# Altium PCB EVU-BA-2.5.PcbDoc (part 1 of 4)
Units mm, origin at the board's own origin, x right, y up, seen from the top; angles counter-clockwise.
Board outline 80 x 82.5 mm, 4 copper layers (Top Layer, Int1, Int2, Bottom Layer), stack 1.49 mm thick; 257 components, 201 nets, 889 pads, 696 vias.
Unrouted connection lines stored in the file: 1.
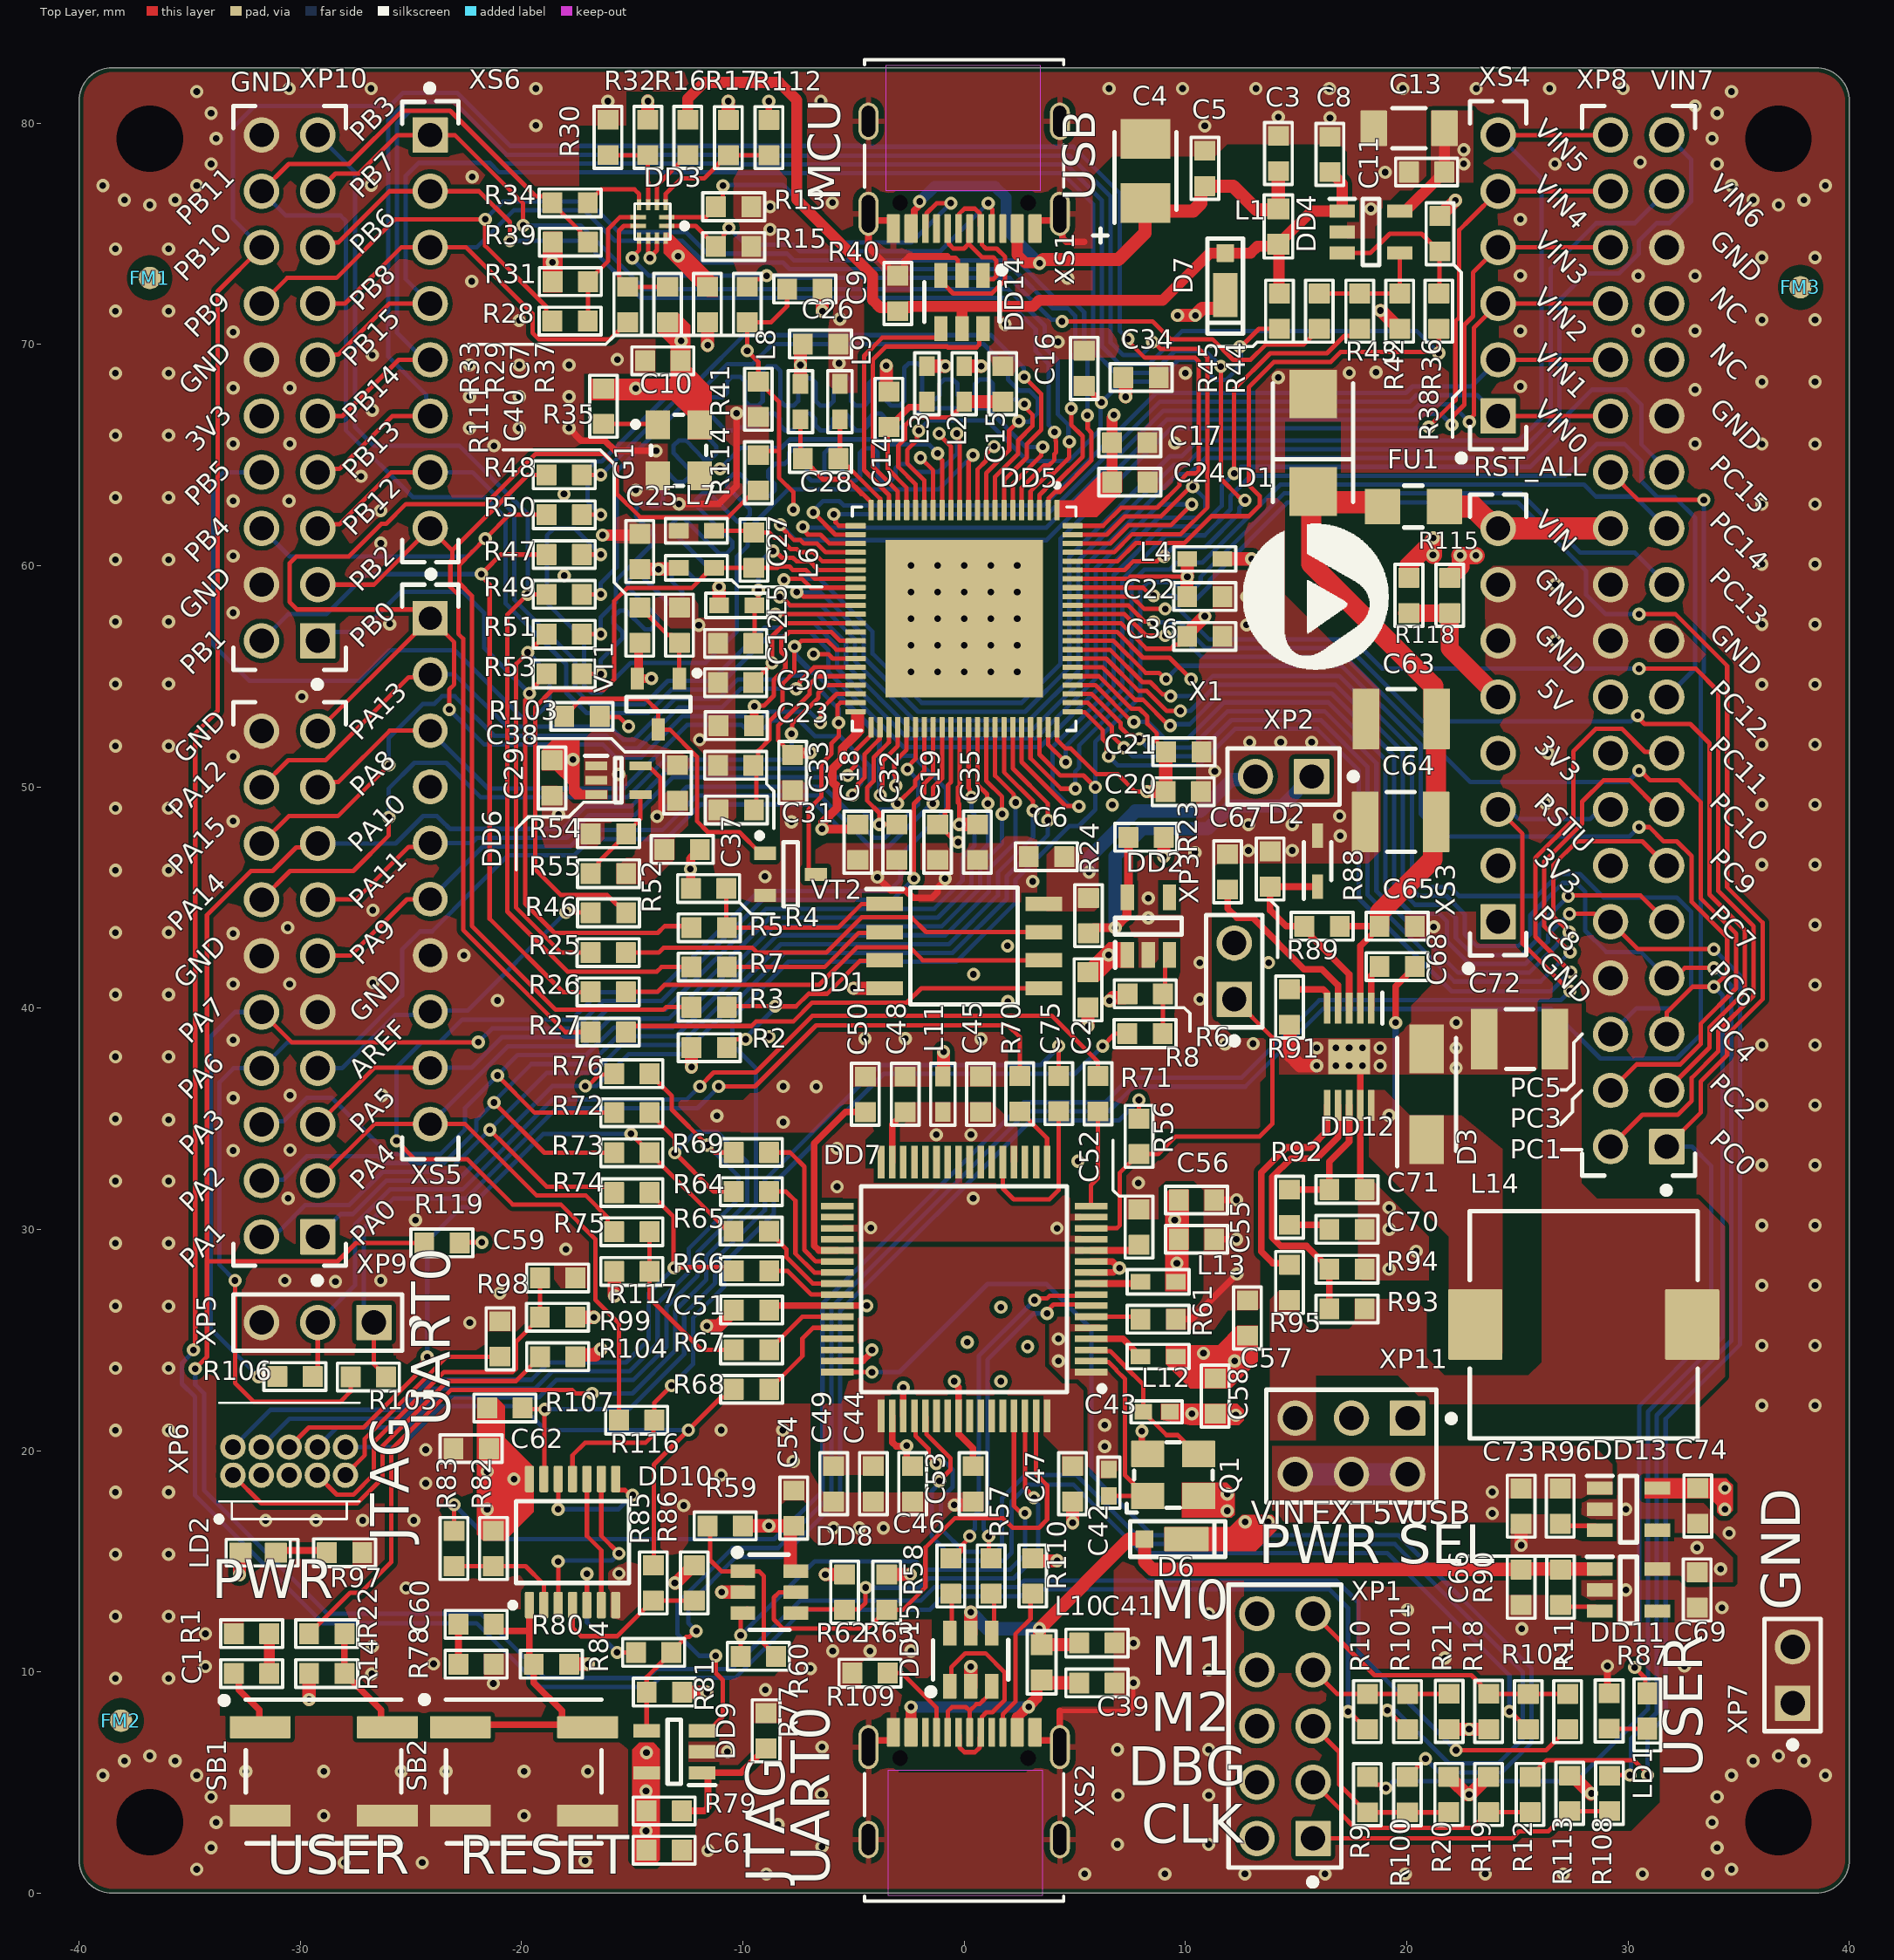
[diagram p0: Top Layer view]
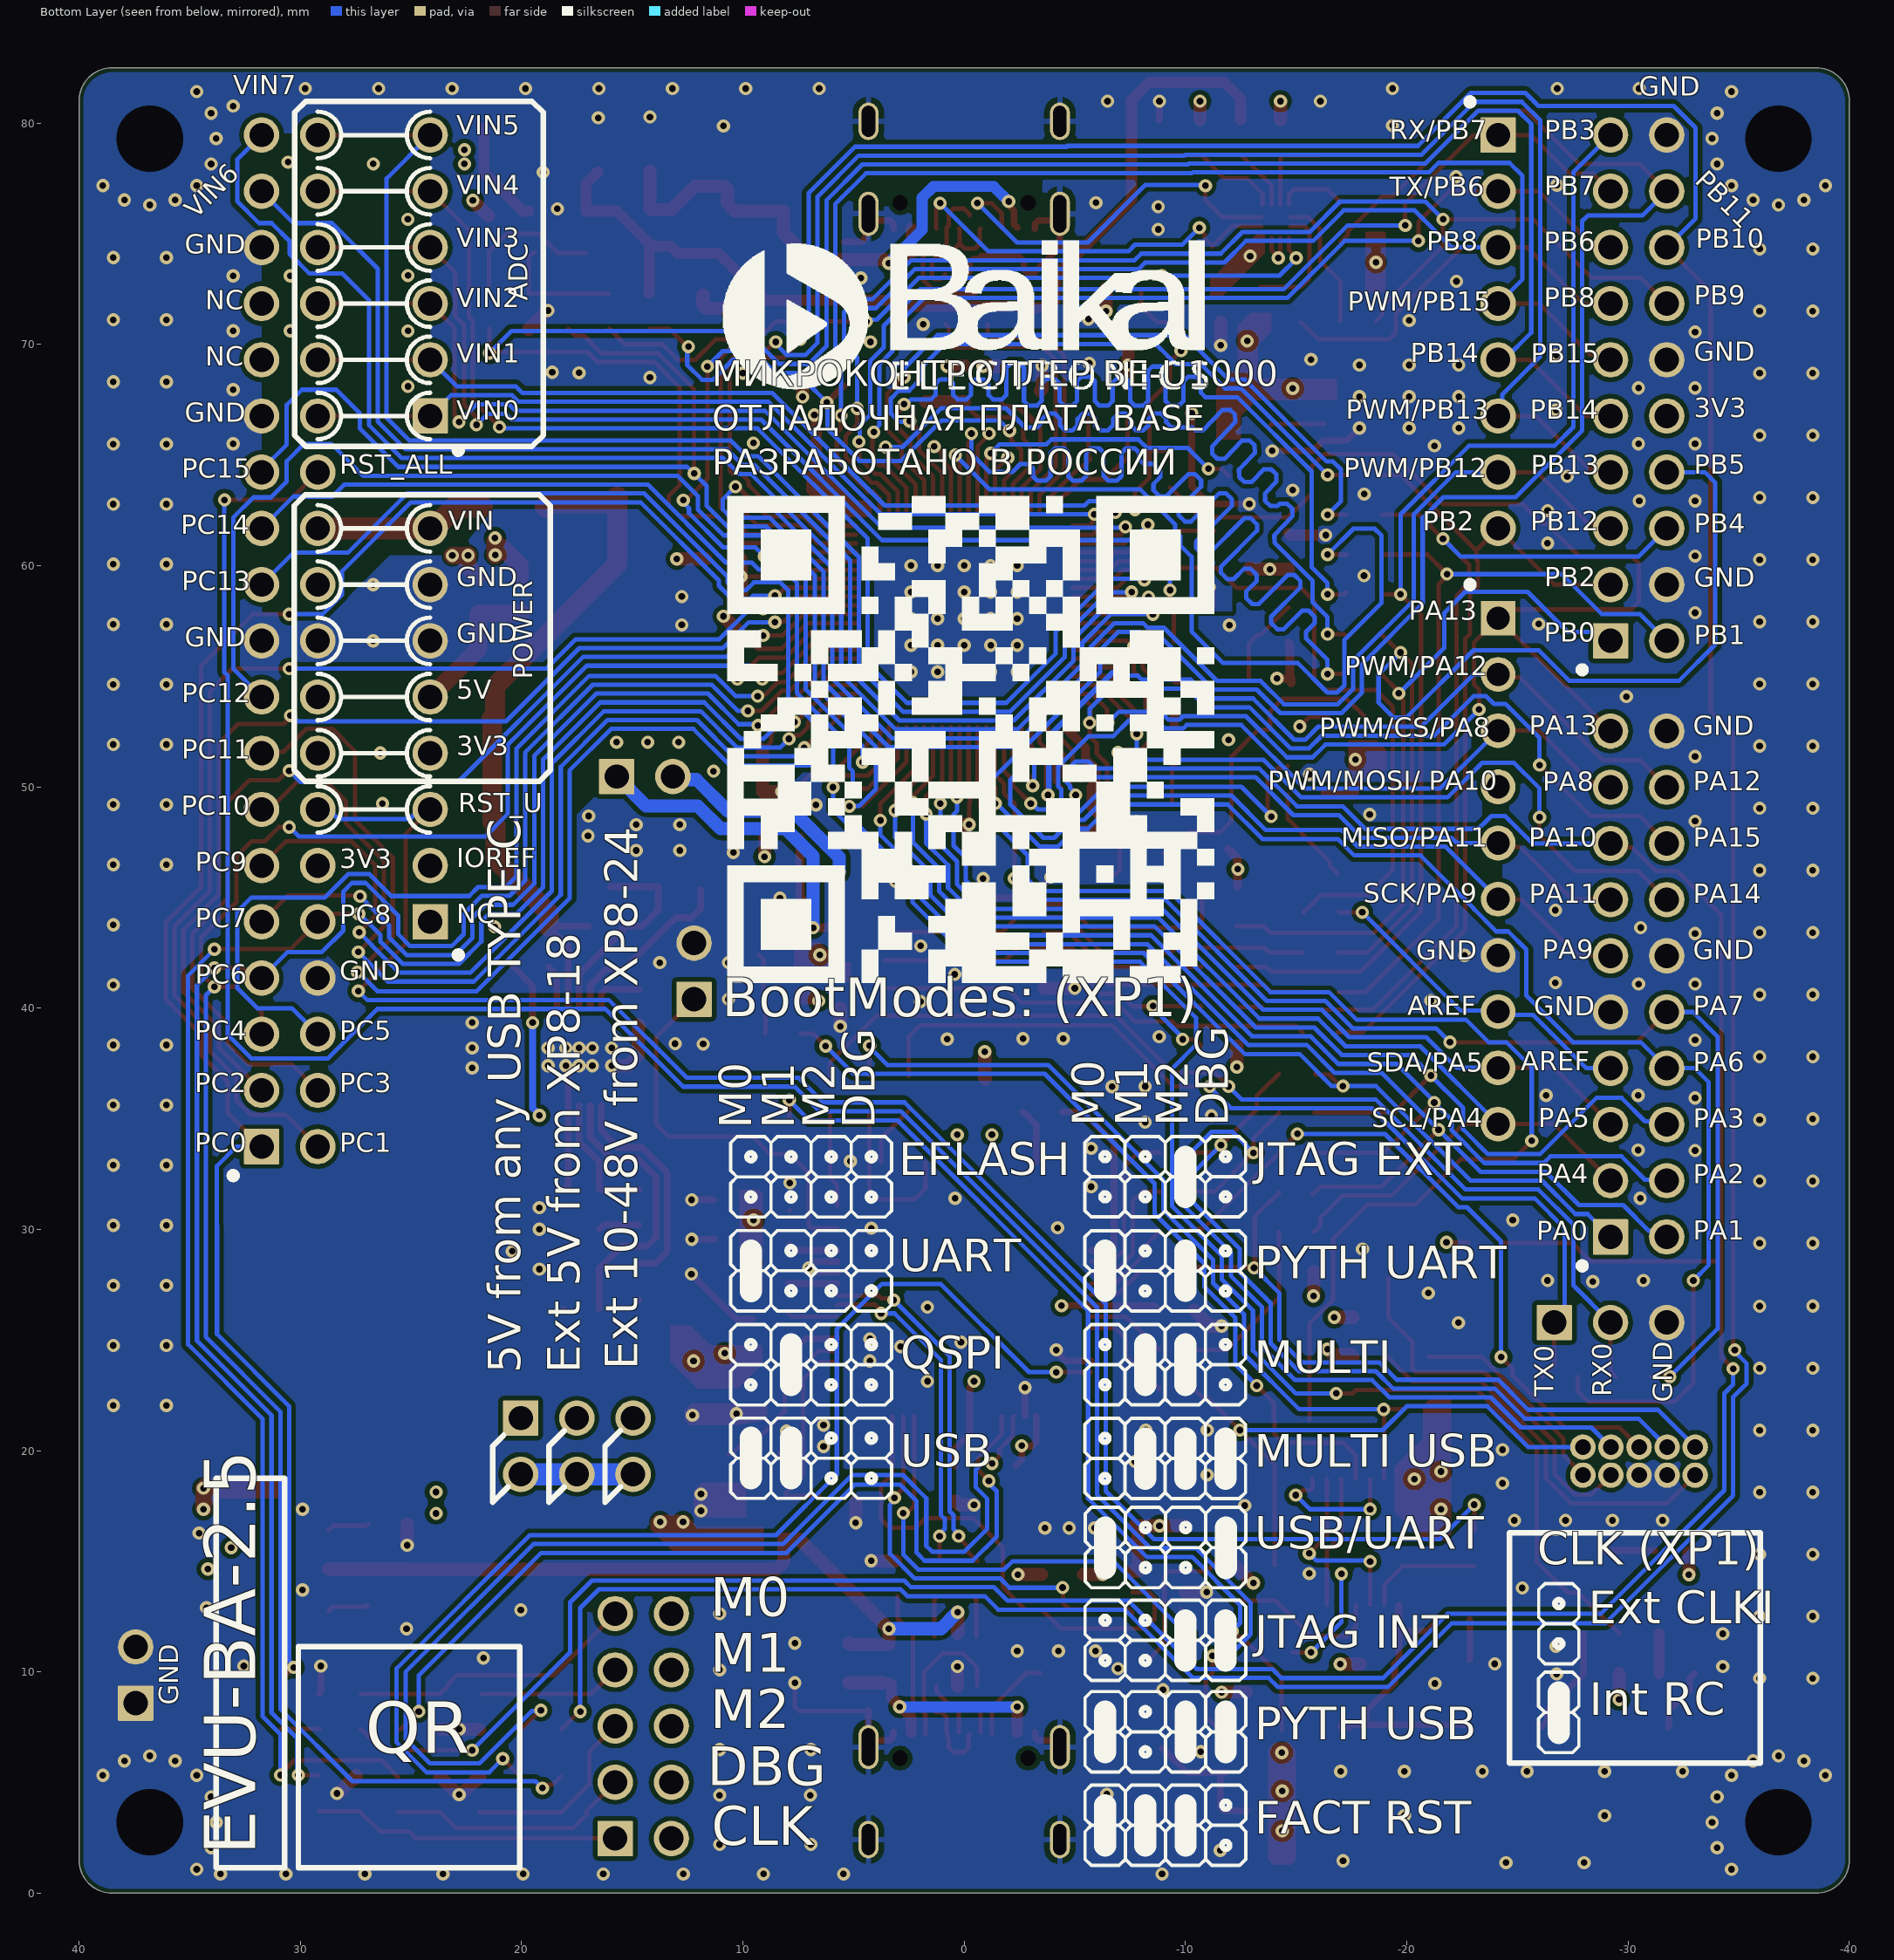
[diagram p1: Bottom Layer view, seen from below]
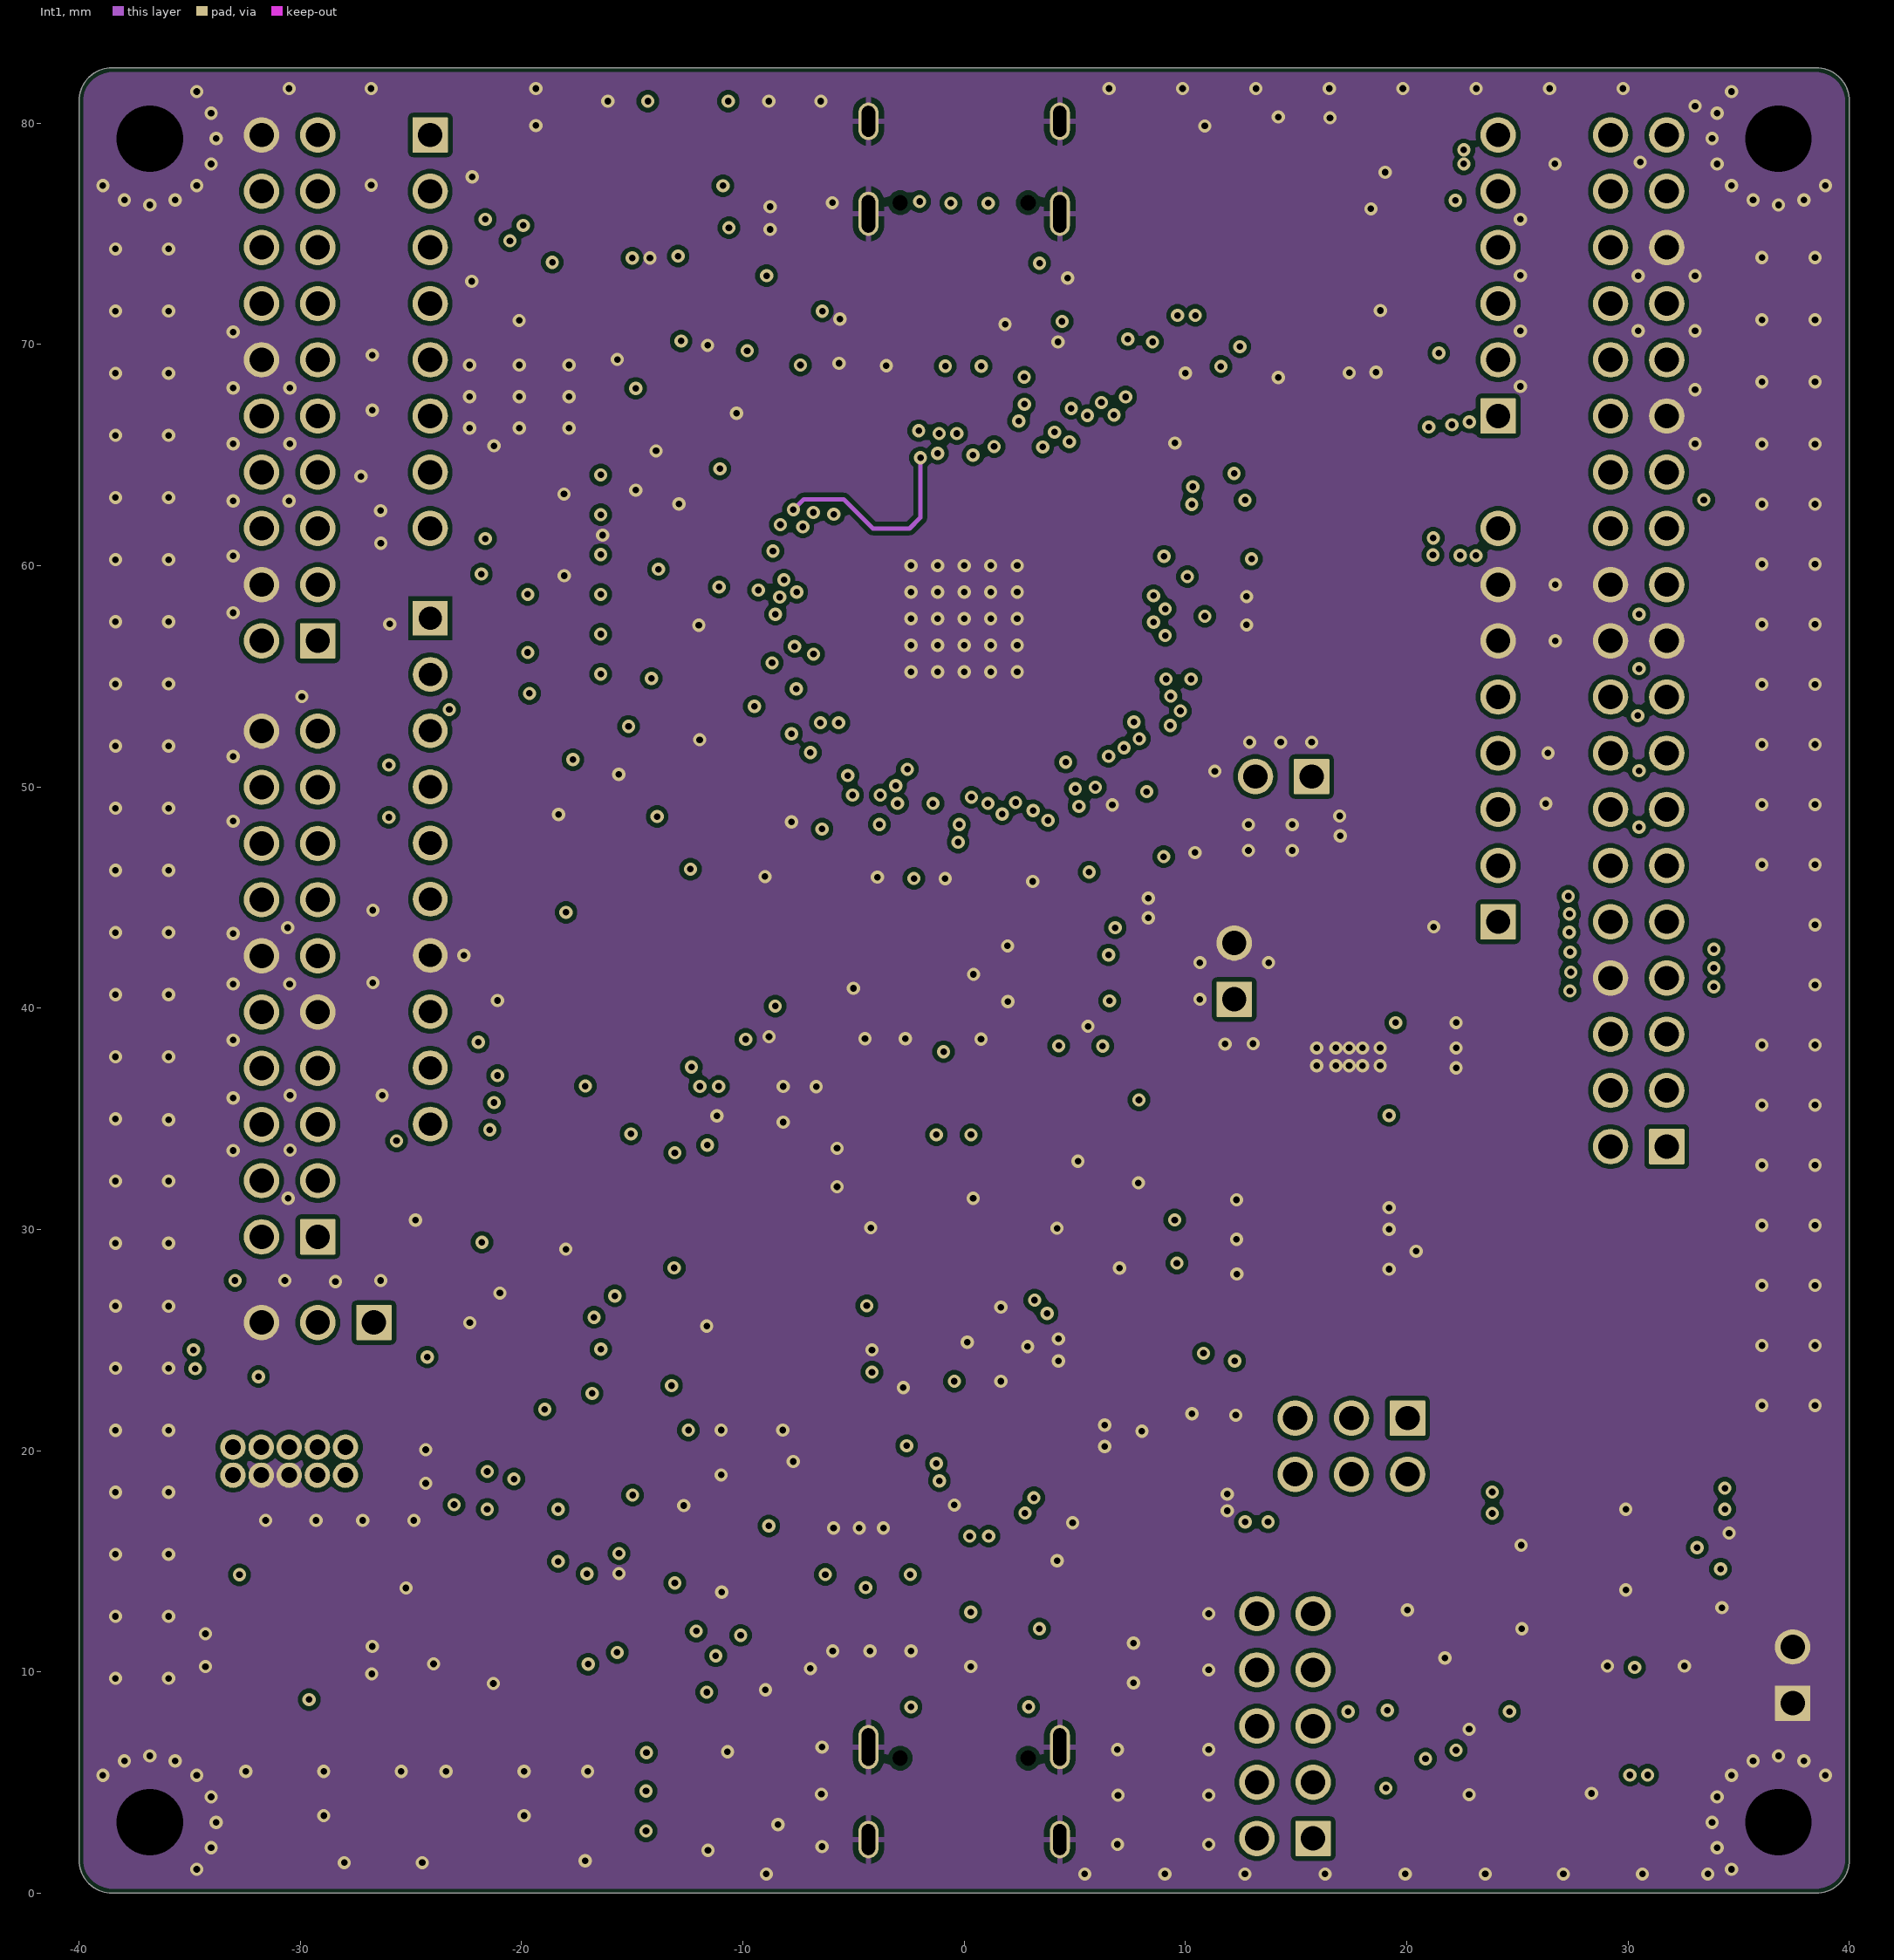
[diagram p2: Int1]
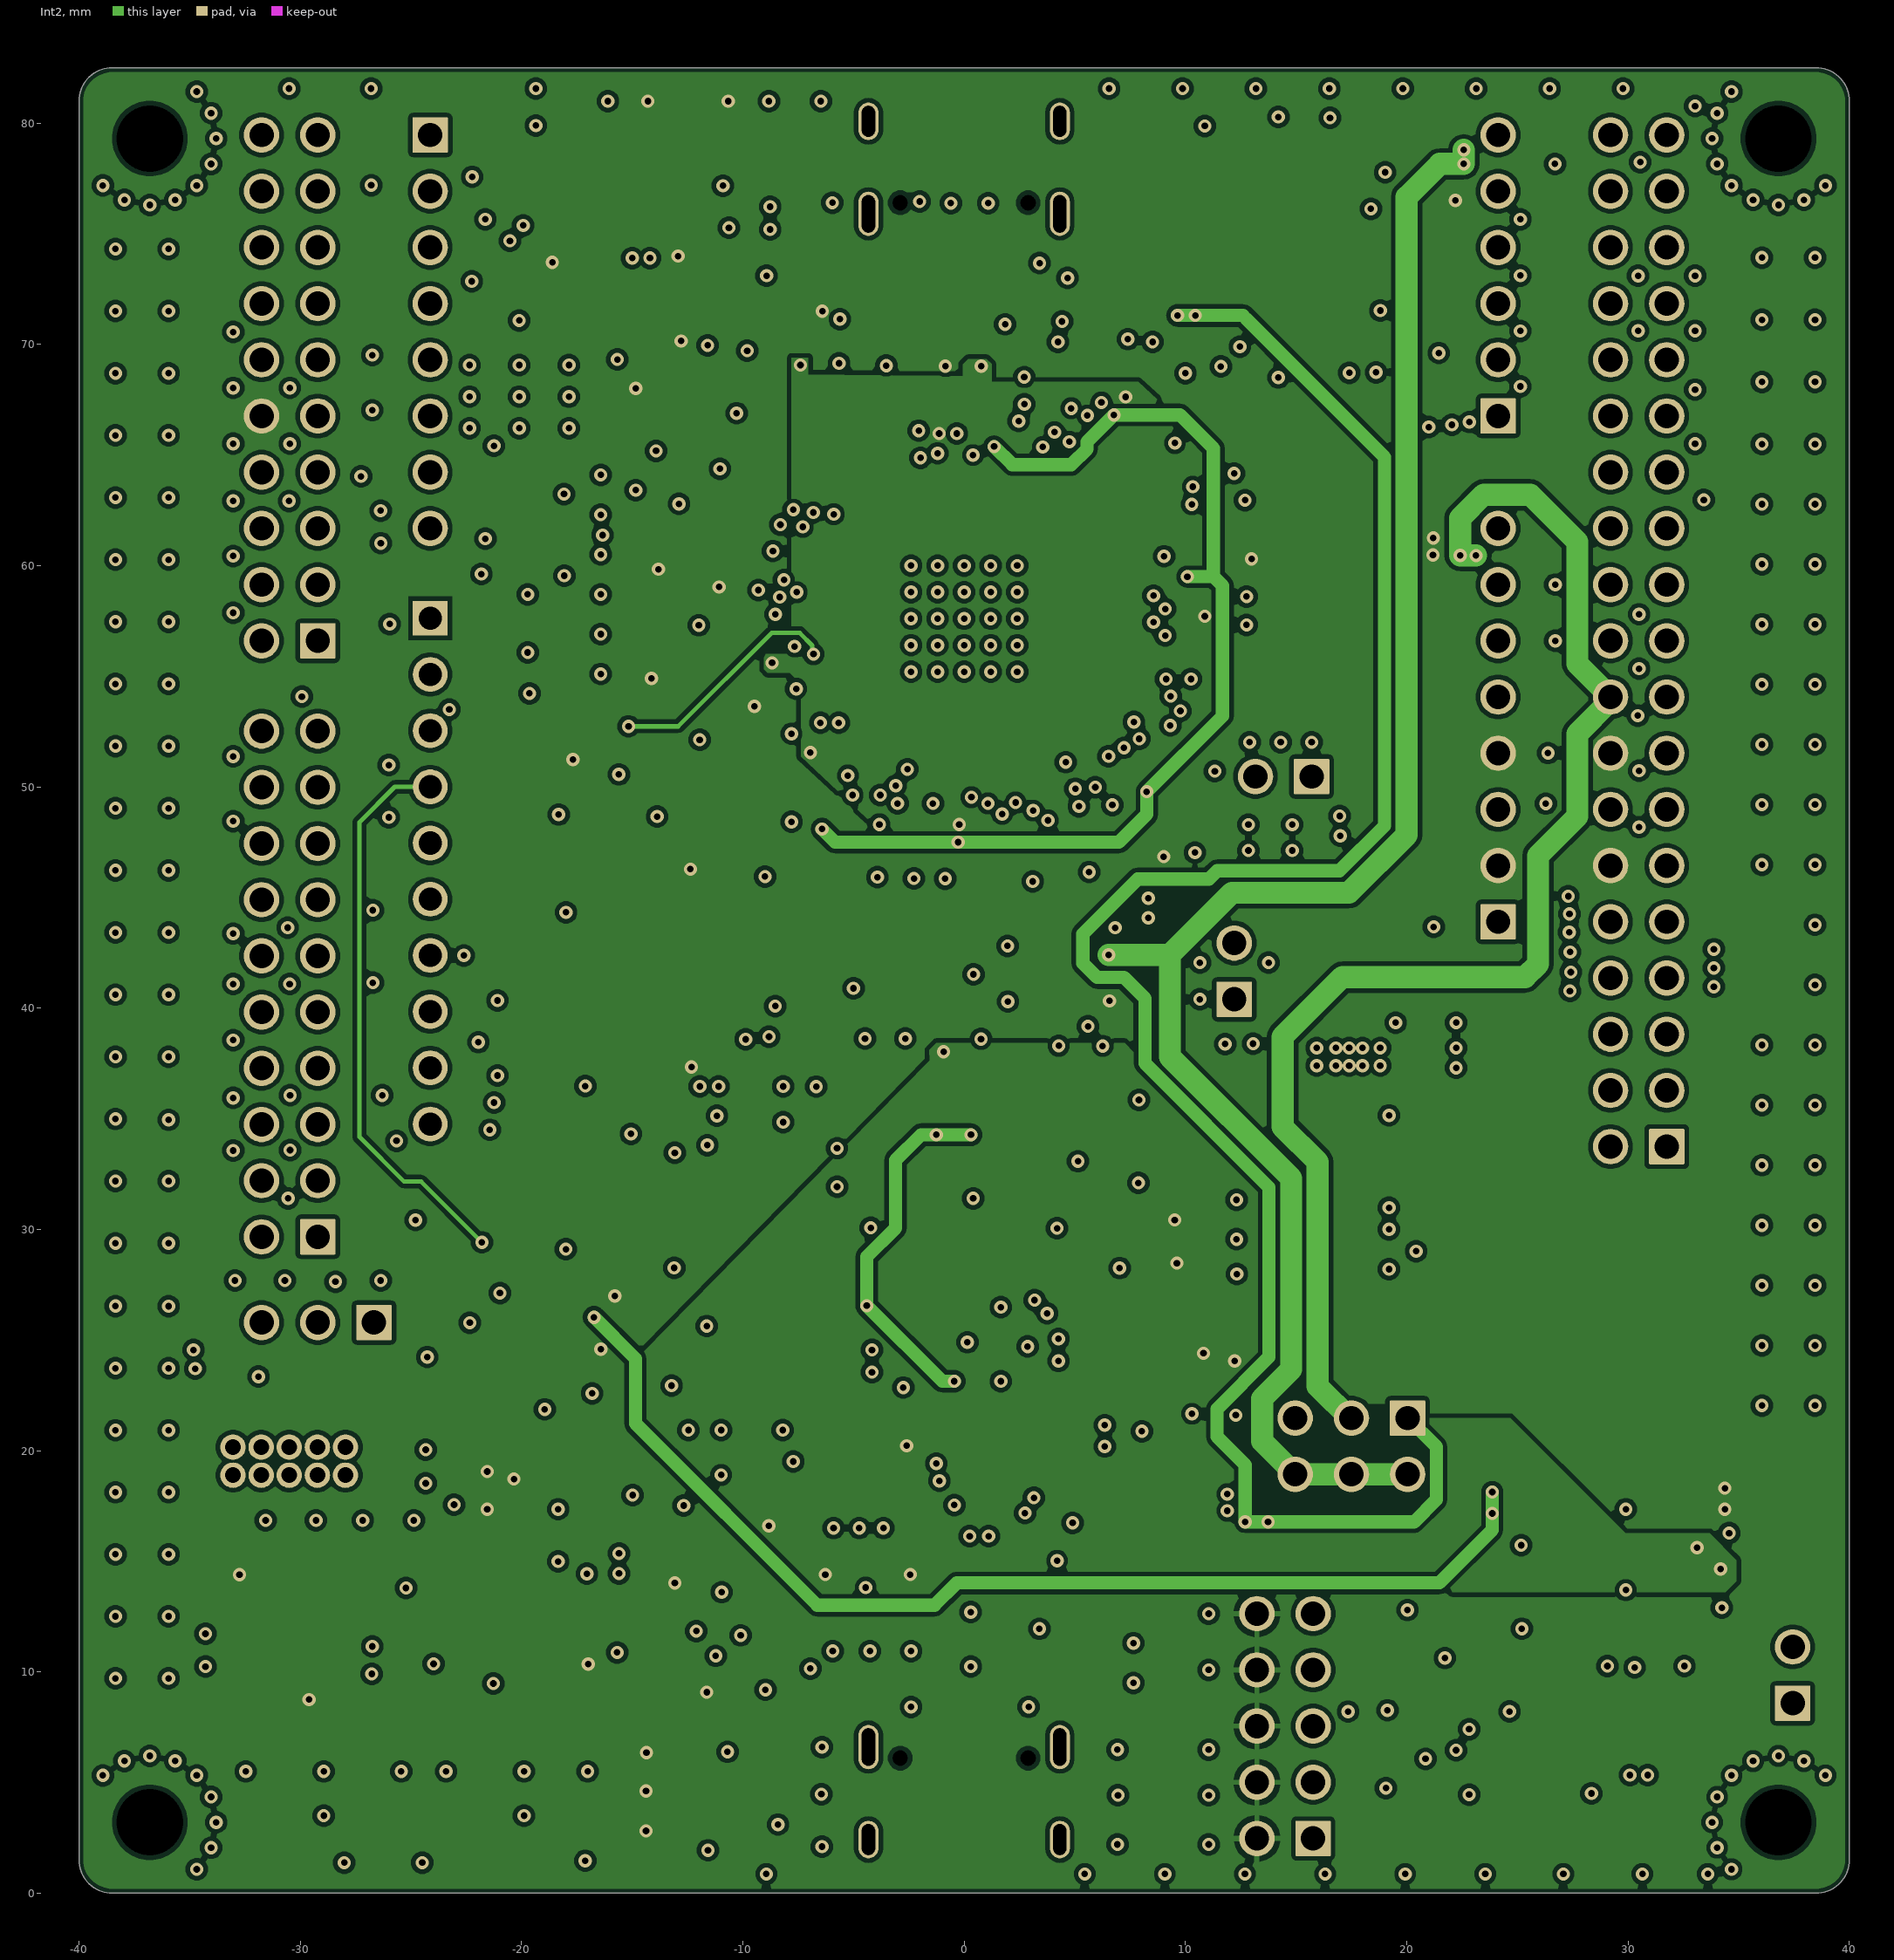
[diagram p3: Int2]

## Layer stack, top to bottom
Top Solder: solder mask 0.0254, SM-001, Dk 3.5
Top Layer: signal copper 0.035
Dielectric 1: prepreg 0.127, FR4, Dk 4.2
Dielectric 2: prepreg 0.193, FR4, Dk 4.6
Int1: signal copper 0.035
Dielectric 3: core 0.71, FR4, Dk 4.6
Int2: signal copper 0.035
Dielectric 4: prepreg 0.193, FR4, Dk 4.6
Dielectric 5: prepreg 0.127, FR4, Dk 4.2
Bottom Layer: signal copper 0.035
Bottom Solder: solder mask 0.0254, SM-001, Dk 3.5

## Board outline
-40,1.5 -40,81 cw(c-38.5,81) -38.5,82.5 38.5,82.5 cw(c38.5,81) 40,81 40,1.5 cw(c38.5,1.5) 38.5,0 -38.5,0 cw(c-38.5,1.5)

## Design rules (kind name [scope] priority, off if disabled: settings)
BoardOutlineClearance [All] p1: gap=0.2 ignorepadtopadclearanceinfootprint=FALSE except(0: Arc-SplitContinuation Track-SplitContinuation SMDPad-SplitContinuation THPad-SplitContinuation Via-SplitContinuation Fill-SplitContinuation Poly-SplitContinuation Region-SplitContinuation Text-SplitContinuation)
Clearance Clearance_CLK [InNet('QSPI1_SCK/PB1')] p1: gap=0.2 ignorepadtopadclearanceinfootprint=TRUE except(0.6: Arc-Arc Arc-Track Arc-Via Arc-Text Track-Track Track-Via Track-Text)
Clearance [All] p2: gap=0.2 ignorepadtopadclearanceinfootprint=TRUE except(0.15: Arc-SMDPad Track-SMDPad SMDPad-SMDPad)
ComponentClearance [All] p1: gap=0.01 collisioncheckmode=3 verticalgap=0 showdistances=FALSE
DiffPairsRouting [All] p1: maxlimit=0.254 minlimit=0.2 mostfreqgap=0.254 toplayer_maxgap=0.2 toplayer_prefgap=0.2 toplayer_minwidth=0.2 toplayer_maxwidth=0.2 toplayer_prefwidth=0.2 midlayer1_minwidth=0.381 midlayer1_maxwidth=0.381 midlayer1_prefwidth=0.381 midlayer2_minwidth=0.381 midlayer2_maxwidth=0.381 midlayer2_prefwidth=0.381 bottomlayer_maxgap=0.2 bottomlayer_prefgap=0.2 bottomlayer_minwidth=0.2 bottomlayer_maxwidth=0.2 bottomlayer_prefwidth=0.2 impedanceprofiledriven=TRUE maxuncoupledlength=12.7
HoleSize [All] p1: absolutevalues=TRUE maxlimit=3 minlimit=0.025 maxpercent=80.000 minpercent=20.000
HoleToHoleClearance [All] p1: gap=0.2 allowstackedmicrovias=TRUE
MatchedLengths QSPI_MatchedLengths [InxSignalClass('QSPI')] p1: tolerance=3.8 checknetsindiffpair=FALSE checkdiffpairvsdiffpair=TRUE checkxsignals=TRUE checkothers=TRUE targetsourcename=PB1-QSPI1_SCK
MatchedLengths DiffPair_MatchedLengths [InDifferentialPair ('USB')] p2: tolerance=25.4 checknetsindiffpair=FALSE checkdiffpairvsdiffpair=TRUE checkxsignals=TRUE checkothers=TRUE
MinimumSolderMaskSliver [All] p1: minsoldermaskwidth=0.2
PolygonConnect PolygonConnect_1 [InComponent('XP1') or InComponent('XS1') or InComponent('XS2')] p1: connectstyle=Relief reliefconductorwidth=0.25 reliefentries=4 polygonreliefangle="90 Angle" airgapwidth=0.25
PolygonConnect ThermalPolygonConnect [All] p2: connectstyle=Direct reliefconductorwidth=0.254 reliefentries=4 polygonreliefangle="90 Angle" airgapwidth=0.254
PolygonConnect [All] p3: connectstyle=Direct reliefconductorwidth=0.254 reliefentries=4 polygonreliefangle="90 Angle" airgapwidth=0.254
RoutingVias [All] p1: holewidth=0.3 width=0.6 viastyle="Through Hole" minholewidth=0.3 minwidth=0.6 maxholewidth=1 maxwidth=1.3
SilkToSolderMaskClearance [IsPad] p1: minsilkscreentomaskgap=0.2 clearancetoexposedcopper=TRUE
SolderMaskExpansion [All] p1: expansion=0.102 istentingtop=FALSE
UnpouredPolygon [All] p1: allowunpoured=TRUE allowshelved=TRUE
Width Width_QSPI [InNetClass('QSPI')] p1: maxlimit=0.2 minlimit=0.142 preferedwidth=0.2 toplayer_minwidth=0.2 bottomlayer_minwidth=0.2 impedanceprofiledriven=TRUE minimp=50.000000 maximp=50.000000 favimp=50.000000
Width [All] p2: maxlimit=1 minlimit=0.2 preferedwidth=0.2 minimp=50.000000 maximp=50.000000 favimp=50.000000
23 further rules are at their usual default settings.

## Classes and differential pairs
component class U_EVU-BA-2.4_Sheet5: C63 C64 C65 C66 C67 C68 C69 C70 C71 C72 C73 C74 D1 D2 D3 D6 D7 DD11 DD12 DD13 FU1 L14 LD2 R88 R89 R90 R91 R92 R93 R94 R95 R96 R97 VD7 XP11
component class U_EVU-BA-2.4_Sheet4: C60 C61 C62 DD9 DD10 LD1 R77 R78 R79 R80 R81 R82 R83 R84 R85 R86 R87 R107 R115 R118 R119 SB2 XP7 XP8 XP9 XP10 XS3 XS4 XS5 XS6
component class U_EVU-BA-2.4_Sheet2: C1 C2 C3 C4 C5 C6 C7 C8 C9 C10 C11 C12 C13 C14 C15 C16 C17 C18 C19 C20 C21 C22 C23 C24 C25 C26 C27 C28 C29 C30 C31 C32 C33 C34 C35 C36 C37 C38 C40 DD1 DD2 DD3 DD4 DD5 DD6 DD14 G1 L1 L2 L3 L4 L5 L6 L7 L8 L9 R1 R2 R3 R4 R5 R6 R7 R8 R9 R10 R11 R12 R13 R14 R15 R16 R17 R18 R19 R20 R21 R22 R23 R24 R25 R26 R27 R28 R29 R30 R31 R32 R33 R34 R35 R36 R37 R38 R39 R40 R41 R42 R43 R44 R45 R46 R47 R48 R49 R50 R51 R52 R53 R54 R55 R103 R108 R111 R112 R113 R114 R116 RESET SB1 USER VT1 VT2 X1 XP1 XP2 XS1
component class U_EVU-BA-2.4_Sheet3: C39 C41 C42 C43 C44 C45 C46 C47 C48 C49 C50 C51 C52 C53 C54 C55 C56 C57 C58 C59 C75 DD7 DD8 DD15 L10 L11 L12 L13 Q1 R56 R57 R58 R59 R60 R61 R62 R63 R64 R65 R66 R67 R68 R69 R70 R71 R72 R73 R74 R75 R76 R98 R99 R100 R101 R102 R104 R105 R106 R109 R110 R117 XP3 XP5 XP6 XS2
differential pair USB: +USB_P -USB_N
differential pair MK: +MK_P -MK_N
differential pair MK_USB: +MK_USB_P -MK_USB_N
differential pair FT: +FT_P -FT_N
differential pair FT_USB: +FT_USB_P -FT_USB_N

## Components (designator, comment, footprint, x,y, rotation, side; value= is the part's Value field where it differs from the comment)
C1 "C0603C104K5RAC" CAPC1608X80N -32.201,9.922 r180 top value=100nF
C2 "GRM188R71C105KA12D" CAPC1608X80N 5.596,40.826 r270 top value=1uF
C3 "C0603C104K5RAC" CAPC1608X80N 14.2,78.625 r90 top value=100nF
C4 "293D106X0020B2TE3" CAPPM3528X210N 8.188,77.836 r90 top value=10uF
C5 "GRM188R71C105KA12D" CAPC1608X80N 10.875,77.95 r270 top value=1uF
C6 "GRM188R71C105KA12D" CAPC1608X80N 3.724,46.845 r180 top value=1uF
C7 "C0603C104K5RAC" CAPC1608X80N -11.6,71.8 r270 top value=100nF
C8 "GRM188R71C105KA12D" CAPC1608X80N 16.531,78.585 r270 top value=1uF
C9 "C0603C104K5RAC" CAPC1608X80N -3,72.3 r90 top value=100nF
C10 "C0603C104K5RAC" CAPC1608X80N -13.615,69.254 r180 top value=100nF
C11 "C0603C104K5RAC" CAPC1608X80N 20.901,77.785 r180 top value=100nF
C12 "C0603C104K5RAC" CAPC1608X80N -10.328,56.48 r0 top value=100nF
C13 "GRM31CR71E106KA12L" CAPC3216X160N 20.107,79.766 r0 top value=10uF
C14 "C0603C104K5RAC" CAPC1608X80N -3.4,67.062 r90 top value=100nF
C15 "C0603C104K5RAC" CAPC1608X80N 1.745,68.212 r90 top value=100nF
C16 "C0603C104K5RAC" CAPC1608X80N 5.423,68.912 r270 top value=100nF
C17 "C0603C104K5RAC" CAPC1608X80N 7.48,65.553 r0 top value=100nF
C18 "C0603C104K5RAC" CAPC1608X80N -4.805,47.5 r270 top value=100nF
C19 "C0603C104K5RAC" CAPC1608X80N -1.2,47.5 r270 top value=100nF
C20 "C0603C104K5RAC" CAPC1608X80N 9.901,49.78 r0 top value=100nF
C21 "C0603C104K5RAC" CAPC1608X80N 9.925,51.582 r0 top value=100nF
C22 "C0603C104K5RAC" CAPC1608X80N 10.875,58.6 r0 top value=100nF
C23 "C0603C104K5RAC" CAPC1608X80N -10.3,52.762 r0 top value=100nF
C24 "C0603C104K5RAC" CAPC1608X80N 7.486,63.77 r0 top value=100nF
C25 "C0603C104K5RAC" CAPC1608X80N -14.658,60.635 r270 top value=100nF
C26 "C0603C104K5RAC" CAPC1608X80N -6.489,70.014 r180 top value=100nF
C27 "GRM188R71C105KA12D" CAPC1608X80N -9.5,60.7 r270 top value=1uF
C28 "GRM188R71C105KA12D" CAPC1608X80N -6.489,64.835 r180 top value=1uF
C29 "C0603C104K5RAC" CAPC1608X80N -18.625,50.4 r90 top value=100nF
C30 "GRM188R71C105KA12D" CAPC1608X80N -10.325,54.713 r180 top value=1uF
C31 "GRM188R71C105KA12D" CAPC1608X80N -10.328,50.975 r180 top value=1uF
C32 "C0603C104K5RAC" CAPC1608X80N -3.045,47.5 r90 top value=100nF
C33 "C0603C104K5RAC" CAPC1608X80N -7.748,50.648 r90 top value=100nF
C34 "C0603C104K5RAC" CAPC1608X80N 7.994,68.5 r180 top value=100nF
C35 "C0603C104K5RAC" CAPC1608X80N 0.6,47.5 r90 top value=100nF
C36 "C0603C104K5RAC" CAPC1608X80N 10.875,56.8 r180 top value=100nF
C37 "C0603C104K5RAC" CAPC1608X80N -10.3,48.95 r0 top value=100nF
C38 "GRM188R71E474KA12D" CAPC1608X80N -12.95,50.175 r90 top value=470nF
C39 "C0603C104K5RAC" CAPC1608X80N 6,9.5 r0 top value=100nF
C40 "GRM188R71C105KA12D" CAPC1608X80N -12.866,57.305 r90 top value=1uF
C41 "C0603C104K5RAC" CAPC1608X80N 6,11.3 r0 top value=100nF
C42 "GRM1555C1H150JA01D" CAPC1005X50N 6.54,18.55 r270 top value=15pF
C43 "GRM1555C1H150JA01D" CAPC1005X50N 8.698,21.75 r180 top value=15pF
C44 "GRM188R60J475KE19D" CAPC1608X80N -4.1,18.5 r90 top value=4.7uF
C45 "C0603C104K5RAC" CAPC1608X80N 0.738,36.109 r270 top value=100nF
C46 "C0603C104K5RAC" CAPC1608X80N -2.325,18.5 r90 top value=100nF
C47 "C0603C104K5RAC" CAPC1608X80N 4.9,18.5 r270 top value=100nF
C48 "C0603C104K5RAC" CAPC1608X80N -2.662,36.102 r270 top value=100nF
C49 "C0603C104K5RAC" CAPC1608X80N -5.9,18.5 r90 top value=100nF
C50 "C0603C104K5RAC" CAPC1608X80N -4.465,36.102 r90 top value=100nF
C51 "C0603C104K5RAC" CAPC1608X80N -9.611,26.349 r0 top value=100nF
C52 "C0603C104K5RAC" CAPC1608X80N 7.9,30.1 r90 top value=100nF
C53 "C0603C104K5RAC" CAPC1608X80N 0.4,18.5 r90 top value=100nF
C54 "C0603C104K5RAC" CAPC1608X80N -7.7,17.4 r90 top value=100nF
C55 "C0603C104K5RAC" CAPC1608X80N 10.5,29.55 r180 top value=100nF
C56 "GRM188R60J475KE19D" CAPC1608X80N 10.5,31.325 r180 top value=4.7uF
C57 "C0603C104K5RAC" CAPC1608X80N 12.8,25.992 r270 top value=100nF
C58 "GRM188R60J475KE19D" CAPC1608X80N 11.34,22.465 r90 top value=4.7uF
C59 "C0603C104K5RAC" CAPC1608X80N -18.371,27.805 r180 top value=100nF
C60 "C0603C104K5RAC" CAPC1608X80N -22.051,12.147 r180 top value=100nF
C61 "C0603C104K5RAC" CAPC1608X80N -13.555,1.937 r180 top value=100nF
C62 "C0603C104K5RAC" CAPC1608X80N -22.276,20.09 r0 top value=100nF
C63 "GCJ32DR72A225KA01" CAPC3225X200N 19.751,53.072 r0 top value=2.2uF
C64 "GCJ32DR72A225KA01" CAPC3225X200N 19.725,48.414 r0 top value=2.2uF
C65 "C0603C104K5RAC" CAPC1608X80N 19.568,43.695 r180 top value=100nF
C66 "GRM188R71C105KA12D" CAPC1608X80N 25.17,13.825 r90 top value=1uF
C67 "C0603C104K5RAC" CAPC1608X80N 11.905,46.157 r270 top value=100nF
C68 "C0603C104K5RAC" CAPC1608X80N 19.568,41.875 r0 top value=100nF
C69 "GRM188R71C105KA12D" CAPC1608X80N 33.124,13.7 r90 top value=1uF
C70 "GRM188R71H333KA61D" CAPC1608X80N 17.3,30 r180 top value=33nF
C71 "C0603C150K4RAC" CAPC1608X80N 17.3,31.8 r180 top value=15pF
C72 "GRM32ER71A476ME15L" CAPC3225X250N 25.1,38.6 r0 top value=47uF
C73 "GRM188R71C105KA12D" CAPC1608X80N 25.17,17.49 r90 top value=1uF
C74 "GRM188R71C105KA12D" CAPC1608X80N 33.15,17.5 r90 top value=1uF
C75 "C0603C104K5RAC" CAPC1608X80N 4.276,36.134 r270 top value=100nF
D1 "SMBJ48A" SMBJ12A 15.769,65.55 r90 top
D2 "BZX84J-B4V7" SOD2512X80N 15.974,46.64 r90 top
D3 "B360A-E3_61T" DIOM5127X229N 20.9,36.1 r90 top
D6 "MSS1P2L-M3" MicroSMP27X14X7 9.4,16 r180 top
D7 "MSS1P2L-M3" MicroSMP27X14X7 11.8,72.875 r90 top
DD1 "MT25QL128ABA1ESE" SOIC127P790X216-8N 0,42.8 r0 top locked
DD2 "AP2112K-3.3TRG1" SOT95P285X140-5N 8.325,43.705 r90 top
DD3 "TUSB320RWBR" TUSB320RWBR -14.086,75.552 r180 top
DD4 "AP2191WG-7" SOT95P285X140-5N 18.382,75.075 r0 top
DD5 "BE-U1000" QFNWB10X10-88L-AL 0,57.6 r270 top locked
DD6 "ZXRE160H5TA" SOT65P210X110-5N -15.625,50.3 r0 top
DD7 "FT2232HL-REEL" QFP50P1200X1200X160-64N 0,27.3 r180 top locked
DD8 "93LC56BT-E_OT" SOT95P280X145-6N -8.8,13.6 r0 top
DD9 "TPS3838K33DBVT" SOT95P280X145-5N -13.1,6.387 r180 top
DD10 "SN74AC08PWR" PW0014A_L -17.697,15.867 r90 top
DD11 "AP2112K-3.3TRG1" SOT95P285X140-5N 30.025,13.7 r0 top
DD12 "TPS54160DGQ" SOP50P490X110-11N 17.4,37.8 r270 top
DD13 "AP2112K-3.3TRG1" SOT95P285X140-5N 30.025,17.35 r0 top
DD14 "USBLC6-2SC6" SOT95P280X145-6N -0.1,71.911 r270 top
DD15 "USBLC6-2SC6" SOT95P280X145-6N 0.295,10.55 r90 top
FM1 "Comment" FIDUCIAL_MARK_2MM -36.8,73 r0 top
FM2 "Comment" FIDUCIAL_MARK_2MM -38.1,7.796 r0 top
FM3 "Comment" FIDUCIAL_MARK_2MM 37.793,72.58 r0 top
FU1 "046601.5NRHF" FUSE466X32X15X60N 20.3,62.667 r180 top value="1,5 A"
G1 "OT322525MJBA4SL" OT322525MJBA4SL -12.9,65.21 r270 top
L1 "BLM18SG331TN1" INDC1608X95N 14.2,75.325 r270 top value="330 Ohms/100 MHz 1,5A 0,07 Ohms"
L2 "BLM18PG471SN1" BLM18X16X08X60N 0,68.212 r270 top value="470 Ohms/100MHz 1A 0,2 Ohms"
L3 "BLM18PG471SN1" BLM18X16X08X60N -1.683,68.212 r270 top value="470 Ohms/100MHz 1A 0,2 Ohms"
L4 "BLM18PG471SN1" BLM18X16X08X60N 10.875,60.3 r180 top value="470 Ohms/100MHz 1A 0,2 Ohms"
L5 "BLM18PG471SN1" BLM18X16X08X60N -10.275,58.2 r0 top value="470 Ohms/100MHz 1A 0,2 Ohms"
L6 "BLM18PG471SN1" BLM18X16X08X60N -12.1,59.9 r0 top value="470 Ohms/100MHz 1A 0,2 Ohms"
L7 "BLM18PG471SN1" BLM18X16X08X60N -12.1,61.575 r0 top value="470 Ohms/100MHz 1A 0,2 Ohms"
L8 "BLM18PG471SN1" BLM18X16X08X60N -7.4,67.412 r270 top value="470 Ohms/100MHz 1A 0,2 Ohms"
L9 "BLM18PG471SN1" BLM18X16X08X60N -5.615,67.412 r270 top value="470 Ohms/100MHz 1A 0,2 Ohms"
L10 "BLM18SG331TN1" INDC1608X95N 3.5,10.429 r90 top value="330 Ohms/100 MHz 1,5A 0,07 Ohms"
L11 "BLM18PG471SN1" BLM18X16X08X60N -0.962,36.109 r270 top value="470 Ohms/100MHz 1A 0,2 Ohms"
L12 "BLM18PG471SN1" BLM18X16X08X60N 8.767,24.25 r0 top value="470 Ohms/100MHz 1A 0,2 Ohms"
L13 "BLM18PG471SN1" BLM18X16X08X60N 8.767,27.625 r0 top value="470 Ohms/100MHz 1A 0,2 Ohms"
L14 "CDRH105RNP-330NC" CDRH105RNP 28,25.7 r0 top value="33 мкГн"
LD1 "KPT-1608SGC" KPT1608X16X08X75N 30.872,8.233 r270 top
LD2 "KPT-1608PWF-A" KPT1608X16X08X75N -31.901,15.387 r0 top
Q1 "X322512MSB4SI" JXS32X330X270X70N 9.449,18.9 r0 top locked value=12MHz
R1 "CR0603-JW-101-E" RESC1608X45N -32.201,11.722 r0 top value=100R
R2 "CR0603-JW-103-E" RESC1608X45N -11.523,38.209 r0 top value=10K
R3 "CR0603-JW-220-E" RESC1608X45N -11.523,40.039 r180 top value=22R
R4 "CR0603-JW-103-E" RESC1608X45N -11.548,45.405 r0 top value=10K
R5 "CR0603-JW-220-E" RESC1608X45N -11.523,43.63 r180 top value=22R
R6 "CR0603-JW-103-E" RESC1608X45N 8.187,40.645 r0 top value=10K
R7 "CR0603-JW-220-E" RESC1608X45N -11.523,41.855 r180 top value=22R
R8 "CR0603-J/-000-E" RESC1608X45N 8.171,38.845 r0 top value=0R
R9 "CR0603-JW-103-E" RESC1608X45N 18.225,4.45 r270 top value=10K
R10 "CR0603-JW-103-E" RESC1608X45N 18.225,8.203 r270 top value=10K
R11 "CR0603-JW-103-E" RESC1608X45N 27.267,8.206 r270 top value=10K
R12 "CR0603-JW-103-E" RESC1608X45N 25.572,4.456 r270 top value=10K
R13 "CR0603-JW-512-E" RESC1608X45N -10.418,76.219 r180 top value="5,1 кОм"
R14 "CR0603-JW-103-E" RESC1608X45N -28.801,9.922 r180 top value=10K
R15 "CR0603-JW-512-E" RESC1608X45N -10.418,74.419 r180 top value="5,1 кОм"
R16 "CR0603-FX-8873-E" RESC1608X45N -12.491,79.352 r270 top value=887K
R17 "CR0603-JW-103-E" RESC1608X45N -10.659,79.34 r270 top value=10K
R18 "CR0603-JW-104-E" RESC1608X45N 23.699,8.209 r270 top value=100K
R19 "CR0603-JW-104-E" RESC1608X45N 23.697,4.456 r90 top value=100K
R20 "CR0603-JW-104-E" RESC1608X45N 21.9,4.456 r90 top value=100K
R21 "CR0603-JW-104-E" RESC1608X45N 21.917,8.209 r270 top value=100K
R22 "CR0603-J/-000-E" RESC1608X45N -28.801,11.722 r180 top value=0R
R23 "CR0603-J/-000-E" RESC1608X45N 8.219,47.72 r180 top value=0R
R24 "CR0603-J/-000-E" RESC1608X45N 5.621,44.18 r90 top value=0R
R25 "CR0603-JW-220-E" RESC1608X45N -16.085,42.505 r0 top value=22R
R26 "CR0603-JW-220-E" RESC1608X45N -16.085,40.73 r0 top value=22R
R27 "CR0603-JW-220-E" RESC1608X45N -16.085,38.914 r0 top value=22R
R28 "CR0603-JW-220-E" RESC1608X45N -17.808,71.052 r180 top value=22R
R29 "CR0603-JW-472-E" RESC1608X45N -13.4,71.8 r270 top value=4K7
R30 "CR0603-JW-103-E" RESC1608X45N -16.098,79.352 r90 top value=10K
R31 "CR0603-JW-472-E" RESC1608X45N -17.796,72.83 r180 top value=4K7
R32 "CR0603-JW-103-E" RESC1608X45N -14.294,79.352 r90 top value=10K
R33 "CR0603-JW-220-E" RESC1608X45N -15.2,71.8 r270 top value=22R
R34 "CR0603-J/-000-E" RESC1608X45N -17.81,76.393 r180 top value=0R
R35 "CR0603-JW-103-E" RESC1608X45N -16.3,67.2 r270 top value=10K
R36 "CR0603-J/-000-E" RESC1608X45N 21.45,71.5 r270 top value=0R
R37 "CR0603-J/-000-E" RESC1608X45N -9.8,71.8 r270 top value=0R
R38 "CR0603-JW-103-E" RESC1608X45N 21.5,75 r90 top value=10K
R39 "CR0603-JW-204-E" RESC1608X45N -17.797,74.615 r0 top value=200K
R40 "CR0603-JW-204-E" RESC1608X45N -7.2,72.5 r180 top value=200K
R41 "CR0603-JW-204-E" RESC1608X45N -9.3,67.513 r90 top value=200K
R42 "CR0603-JW-104-E" RESC1608X45N 19.682,71.5 r270 top value=100K
R43 "CR0603-J/-000-E" RESC1608X45N 17.879,71.5 r270 top value=0R
R44 "CR0603-J/-000-E" RESC1608X45N 16.05,71.5 r270 top value=0R
R45 "CR0603-JW-102-E" RESC1608X45N 14.25,71.5 r270 top value="1 кОм"
R46 "CR0603-J/-000-E" RESC1608X45N -16.075,44.305 r180 top value=0R
R47 "CR0603-J/-000-E" RESC1608X45N -18.072,60.5 r180 top value=0R
R48 "CR0603-J/-000-E" RESC1608X45N -18.072,64.1 r180 top value=0R
R49 "CR0603-J/-000-E" RESC1608X45N -18.072,58.7 r180 top value=0R
R50 "CR0603-J/-000-E" RESC1608X45N -18.072,62.3 r180 top value=0R
R51 "CR0603-J/-000-E" RESC1608X45N -18.072,56.9 r180 top value=0R
R52 "CR0603-JW-102-E" RESC1608X45N -12.743,47.168 r180 top value="1 кОм"
R53 "CR0603-J/-000-E" RESC1608X45N -18.072,55.1 r180 top value=0R
R54 "CR0603-FX-1502-E" RESC1608X45N -16.075,47.875 r0 top value=15K
R55 "CR0603-FX-1002-E" RESC1608X45N -16.075,46.075 r0 top value=10K
R56 "CR0603-J/-000-E" RESC1608X45N 7.9,34.2 r270 top value=0R
R57 "CR0603-JW-100-E" RESC1608X45N 1.22,14.334 r90 top value=10R
R58 "CR0603-JW-100-E" RESC1608X45N -0.605,14.334 r90 top value=10R
R59 "CR0603-JW-103-E" RESC1608X45N -10.8,16.596 r180 top value=10K
R60 "CR0603-JW-202-E" RESC1608X45N -9.3,10.7 r0 top value=2K
R61 "CR0603-FX-1202-E" RESC1608X45N 8.767,25.94 r180 top value=12K
R62 "CR0603-JW-103-E" RESC1608X45N -5.4,13.6 r270 top value=10K
R63 "CR0603-JW-103-E" RESC1608X45N -3.5,13.6 r270 top value=10K
R64 "CR0603-J/-000-E" RESC1608X45N -9.618,31.704 r180 top value=0R
R65 "CR0603-J/-000-E" RESC1608X45N -9.622,29.918 r180 top value=0R
R66 "CR0603-J/-000-E" RESC1608X45N -9.611,28.126 r180 top value=0R
R67 "CR0603-J/-000-E" RESC1608X45N -9.611,24.55 r180 top value=0R
R68 "CR0603-J/-000-E" RESC1608X45N -9.611,22.77 r180 top value=0R
R69 "CR0603-J/-000-E" RESC1608X45N -9.618,33.473 r180 top value=0R
R70 "CR0603-J/-000-E" RESC1608X45N 2.51,36.127 r90 top value=0R
R71 "CR0603-J/-000-E" RESC1608X45N 6.05,36.127 r90 top value=0R
R72 "CR0603-JW-220-E" RESC1608X45N -15.018,35.271 r180 top value=22R
R73 "CR0603-JW-220-E" RESC1608X45N -15.018,33.459 r180 top value=22R
R74 "CR0603-JW-220-E" RESC1608X45N -15.018,31.659 r180 top value=22R
R75 "CR0603-JW-220-E" RESC1608X45N -15.018,29.893 r180 top value=22R
R76 "CR0603-JW-220-E" RESC1608X45N -15.018,37.034 r180 top value=22R
R77 "CR0603-J/-000-E" RESC1608X45N -8.955,7.337 r270 top value=0R
R78 "CR0603-JW-101-E" RESC1608X45N -22.051,10.347 r180 top value=100R
R79 "CR0603-J/-000-E" RESC1608X45N -13.555,3.717 r180 top value=0R
R80 "CR0603-JW-103-E" RESC1608X45N -18.651,10.347 r0 top value=10K
R81 "CR0603-JW-103-E" RESC1608X45N -13.546,9.082 r0 top value=10K
R82 "CR0603-JW-103-E" RESC1608X45N -21.275,15.575 r90 top value=10K
R83 "CR0603-J/-000-E" RESC1608X45N -23.051,15.575 r90 top value=0R
R84 "CR0603-J/-000-E" RESC1608X45N -14.031,10.878 r0 top value=0R
R85 "CR0603-J/-000-E" RESC1608X45N -14.046,14.017 r270 top value=0R
R86 "CR0603-JW-103-E" RESC1608X45N -12.2,14.017 r90 top value=10K
R87 "CR0603-JW-331-E" RESC1608X45N 29.148,8.233 r270 top value=330R
R88 "CR0603-FX-1543-E" RESC1608X45N 16.174,43.7 r0 top value=154K
R89 "CR0603-FX-2212-E" RESC1608X45N 13.825,46.29 r270 top value=22K1
R90 "CR0603-J/-000-E" RESC1608X45N 26.95,13.825 r270 top value=0R
R91 "CR0603-FX-1543-E" RESC1608X45N 14.7,40.052 r90 top value=154K
R92 "CR0603-FX-8872-E" RESC1608X45N 14.7,31 r90 top value=88K7
R93 "CR0603-FX-5362-E" RESC1608X45N 17.3,26.4 r0 top value=53K6
R94 "CR0603-FX-1002-E" RESC1608X45N 17.3,28.2 r180 top value=10K
R95 "CR0603-FX-1002-E" RESC1608X45N 14.7,27.6 r270 top value=10K
R96 "CR0603-J/-000-E" RESC1608X45N 26.936,17.49 r270 top value=0R
R97 "CR0603-JW-202-E" RESC1608X45N -28.001,15.387 r0 top value=2K
R98 "CR0603-J/-000-E" RESC1608X45N -20.979,25.046 r90 top value=0R
R99 "CR0603-J/-000-E" RESC1608X45N -18.376,26.026 r0 top value=0R
R100 "CR0603-J/-000-E" RESC1608X45N 20.03,4.45 r270 top value=0R
R101 "CR0603-J/-000-E" RESC1608X45N 20.033,8.203 r90 top value=0R
R102 "CR0603-J/-000-E" RESC1608X45N 25.492,8.206 r90 top value=0R
R103 "CR0603-JW-102-E" RESC1608X45N -17.272,53.184 r180 top value="1 кОм"
R104 "CR0603-J/-000-E" RESC1608X45N -18.371,24.246 r180 top value=0R
R105 "CR0603-J/-000-E" RESC1608X45N -26.925,23.328 r180 top value=0R
R106 "CR0603-J/-000-E" RESC1608X45N -30.239,23.344 r180 top value=0R
R107 "CR0603-JW-103-E" RESC1608X45N -20.75,21.925 r180 top value=10K
R108 "CR0603-JW-103-E" RESC1608X45N 29.165,4.506 r270 top value=10K
R109 "CR0603-JW-512-E" RESC1608X45N -4.256,9.944 r180 top value="5,1 кОм"
R110 "CR0603-JW-512-E" RESC1608X45N 3.1,14.334 r90 top value="5,1 кОм"
R111 "CR0603-JW-104-E" RESC1608X45N -14.658,57.303 r90 top value=100K
R112 "CR0603-JW-103-E" RESC1608X45N -8.823,79.34 r270 top value=10K
R113 "CR0603-JW-104-E" RESC1608X45N 27.365,4.506 r90 top value=100K
R114 "CR0603-J/-000-E" RESC1608X45N -9.3,64.194 r90 top value=0R
R115 "CR0603-J/-000-E" RESC1608X45N 21.942,58.65 r90 top value=0R
R116 "CR0603-J/-000-E" RESC1608X45N -14.799,21.377 r180 top value=0R
R117 "CR0603-JW-102-E" RESC1608X45N -15.018,28.099 r0 top value="1 кОм"
R118 "CR0603-J/-000-E" RESC1608X45N 20.1,58.65 r90 top value=0R
R119 "CR0603-J/-000-E" RESC1608X45N -23.597,29.388 r180 top value=0R
SB1 "B3SL-1002P" B3SL-1002P -28.938,5.5 r180 top
SB2 "B3SL-1002P" B3SL-1002P -19.889,5.5 r180 top
VT1 "BSS84" SOT95P230X110-3N -13.821,53.74 r270 top
VT2 "BSS138" SOT95P230X110-3N -7.848,46.043 r0 top
X1 "PAD_SMD25X25" PAD_SMD25X25 10.25,54.872 r180 top
XP1 "DS1021-2x5SF11-B" PLD10-254PX1278X254X854N 14.5,7.55 r270 top
XP2 "DS1021-1x2SF11-B" PLS2-254PX50X25X854N 14.433,50.467 r180 top
XP3 "DS1021-1x2SF11-B" PLS2-254PX50X25X854N 12.205,41.67 r90 top
XP5 "DS1021-1x3SF11-B" PLS3-254PX76X25X854N -29.21,25.789 r180 top
XP6 "FTSH-105-01-F-D-K" FTSH-105-XX-YYY-D-K -33.039,18.888 r0 top
XP7 "DS1021-1x2SF11-B" PLS2-254PX50X25X854N 37.44,9.855 r90 top
XP8 "TSW-119-09-T-D" PLD38-254PX4834X254X854N 30.48,56.6 r270 top locked
XP9 "TSW-110-09-T-D" PLD20-254PX2548X254X854N -30.48,41.09 r270 top
XP10 "TSW-110-09-T-D" PLD20-254PX2548X254X854N -30.48,68.03 r270 top locked
XP11 "DS1021-2x3SF11-B" PLD6-254PX762X508X854N 17.5,20.2 r0 top locked
XS1 "TYPE-C-31-M-12" TYPE-C-31-M-12 3.2,75.33 r180 top locked
XS2 "TYPE-C-31-M-12" TYPE-C-31-M-12 -3.2,7.17 r0 top locked
XS3 "DS1023-1x8S21" "PBS8-254PX200X25X840N - DUPLICATE" 24.13,52.79 r90 top locked
XS4 "DS1023-1x6S21" "PBS6-254PX152X25X840N - DUPLICATE" 24.13,73.11 r90 top locked
XS5 "DS1023-1x10S21" "PBS10-254PX152X25X840N - DUPLICATE" -24.13,57.62 r270 top
XS6 "DS1023-1x8S21" "PBS8-254PX200X25X840N - DUPLICATE" -24.13,70.57 r270 top locked

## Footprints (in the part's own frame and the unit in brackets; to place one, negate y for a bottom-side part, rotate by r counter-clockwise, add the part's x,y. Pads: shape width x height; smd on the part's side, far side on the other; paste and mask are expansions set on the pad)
B3SL-1002P [mm]
  rrect5% 2.75x1 smd mask+0.07: 1(2.875,-2) 2(-2.875,-2) 3(2.875,2) 4(-2.875,2)
  silkscreen extent -3.5,-3.36 4.65,3.25, body extent -3.5,-3.25 3.5,3.25, height 3.4
BLM18X16X08X60N [mm]
  rrect5% 0.9x0.7 smd mask+0.07: 1(-0.8,0) 2(0.8,0)
  silkscreen extent -1.4,-0.55 1.4,0.55, body extent -0.9,-0.5 0.9,0.5, height 1
CAPC1005X50N [mm]
  rrect5% 0.8x0.7 smd paste-25.4 mask+0.07: 1(-0.6,0) 2(0.6,0)
  silkscreen extent -1.15,-0.5 1.15,0.5, body extent -0.53,-0.28 0.53,0.28, height 0.55
CAPC1608X80N [mm]
  rrect5% 0.9x0.95 smd mask+0.07: 1(-0.8,0) 2(0.8,0)
  silkscreen extent -1.4,-0.63 1.4,0.63, body extent -0.9,-0.52 0.9,0.48, height 0.95
CAPC3216X160N [mm]
  rrect5% 1.2x1.6 smd mask+0.07: 1(-1.6,0) 2(1.6,0)
  silkscreen extent -0.75,-0.9 0.75,0.9, body extent -1.55,-0.8 1.55,0.8, height 1.6
CAPC3225X200N [mm]
  rrect5% 1.2x2.75 smd mask+0.07: 1(-1.6,0) 2(1.6,0)
  silkscreen extent -0.63,-1.35 0.65,1.35, body extent -1.6,-1.25 1.6,1.25, height 2
CAPC3225X250N [mm]
  rrect5% 1.2x2.75 smd mask+0.07: 1(-1.6,0) 2(1.6,0)
  silkscreen extent -0.63,-1.35 0.65,1.35, body extent -1.6,-1.25 1.6,1.25, height 2.5
CAPPM3528X210N [mm]
  rect 1.8x2.25 smd: 1(-1.45,0) 2(1.45,0)
  silkscreen extent -3.24,-1.4 1.75,2.35, body extent -1.86,-1.54 1.87,1.53, height 2.13
CDRH105RNP [mm]
  rrect5% 2.45x3.2 smd mask+0.07: 1(-4.9,0) 2(4.9,0)
  silkscreen extent -5.15,-5.15 5.15,5.13, body extent -5.16,-5 5.16,5, height 3.78
DIOM5127X229N [mm]
  rect 2.2x1.55 smd: 1(-2.05,0) 2(2.05,0)
  silkscreen extent -3.24,-1.33 2.55,1.33, body extent -2.55,-1.33 2.55,1.33, height 2.29
FIDUCIAL_MARK_2MM [mil]
  round 40 smd paste+8.28 mask+20: 1(0,0)
  Top Layer pour cut-out: 0,-40 -3.94,-40 -11.67,-38.46 -18.95,-35.45 -25.5,-31.07 -31.07,-25.5 -35.45,-18.95 -38.46,-11.67 -40,-3.94 -40,0 -40,3.94 -38.46,11.67 -35.45,18.95 -31.07,25.5 -25.5,31.07 -18.95,35.45 -11.67,38.46 -3.94,40 0,40 3.94,40 11.67,38.46 18.95,35.45 25.5,31.07 31.07,25.5 35.45,18.95 38.46,11.67 40,3.94 40,0 40,-3.94 38.46,-11.67 35.45,-18.95 31.07,-25.5 25.5,-31.07 18.95,-35.45 11.67,-38.46 3.94,-40 0,-40
FTSH-105-XX-YYY-D-K [mm]
  round 1.15 hole 0.71: 1(0,0) 2(0,1.27) 3(1.27,0) 4(1.27,1.27) 5(2.54,0) 6(2.54,1.27) 7(3.81,0) 8(3.81,1.27) 9(5.08,0) 10(5.08,1.27)
  silkscreen extent -0.76,-2.11 5.71,3.26, body extent -0.64,-1.91 5.71,3.17, height 5.71
FUSE466X32X15X60N [mm]
  rrect5% 1.6x1.6 smd mask+0.05: 1(-1.4,0) 2(1.4,0)
  silkscreen extent -0.4,-0.95 0.4,0.95, body extent -1.65,-0.8 1.65,0.8, height 0.66
INDC1608X95N [mm]
  rrect5% 0.95x1 smd mask+0.07: 1(-0.8,0) 2(0.8,0)
  silkscreen extent -1.43,-0.65 1.43,0.65, body extent -0.87,-0.47 0.88,0.48, height 0.65
JXS32X330X270X70N [mm]
  rrect5% 1.5x1.2 smd mask+0.07: 1(-1.15,-0.95) 2(1.15,-0.95) 3(1.15,0.95) 4(-1.15,0.95)
  silkscreen extent -2.1,-1.7 1.78,1.48, body extent -1.65,-1.35 1.65,1.35, height 0.76
KPT1608X16X08X75N [mm]
  rrect5% 1x0.9 smd mask+0.07: 1(-0.8,0) 2(0.8,0)
  silkscreen extent -1.45,-0.6 1.8,0.6, body extent -0.8,-0.4 0.8,0.4, height 0.76
MicroSMP27X14X7 [mm]
  rrect5% 2x1.1 smd mask+0.07: 1(-0.65,0)
  rrect5% 0.8x0.8 smd mask+0.07: 2(1.25,0)
  silkscreen extent -2.4,-0.8 1.9,0.8, body extent -1.35,-0.7 1.35,0.7, height 0.74
OT322525MJBA4SL [mm]
  rect 1.3x1.1 smd: 1(-1.15,-0.95) 2(1.15,-0.95) 3(1.15,0.95) 4(-1.15,0.95)
  silkscreen extent -1.6,-2.07 1.6,1.25, body extent -1.69,-1.39 1.69,1.39, height 1.1
PAD_SMD25X25 [mm]
  rrect5% 0.25x0.25 smd mask+0.07: 1(0,0)
"PBS6-254PX152X25X840N - DUPLICATE" [mil]
  rrect5% 63x63 hole 43.31 mask+2.76: 1(-250,0)
  round 63 hole 43.31 mask+2.76: 2(-150,0) 3(-50,0) 4(50,0) 5(150,0) 6(250,0)
  silkscreen extent -331,-50 310,71, body extent -310,-50 310,48, height 335
"PBS8-254PX200X25X840N - DUPLICATE" [mil]
  rrect5% 63x63 hole 43.31 mask+2.76: 1(-350,0)
  round 63 hole 43.31 mask+2.76: 2(-250,0) 3(-150,0) 4(-50,0) 5(50,0) 6(150,0) 7(250,0) 8(350,0)
  silkscreen extent -439,-50 410,59, body extent -410,-49 410,49, height 335
"PBS10-254PX152X25X840N - DUPLICATE" [mm]
  rect 1.575x1.575 hole 1.05: 1(0,0)
  round 1.575 hole 1.05: 2(2.54,0) 3(5.08,0) 4(7.62,0) 5(10.16,0) 6(12.7,0) 7(15.24,0) 8(17.78,0) 9(20.32,0) 10(22.86,0)
  silkscreen extent -2.14,-1.27 24.46,1.27, body extent -1.52,-1.25 24.38,1.25, height 8.5
PLD6-254PX762X508X854N [mil]
  rrect5% 63x63 hole 43.31 mask+2.76: 1(100,50)
  round 63 hole 43.31 mask+2.76: 2(100,-50) 3(0,50) 4(0,-50) 5(-100,50) 6(-100,-50)
  silkscreen extent -152,-100 183,100, body extent -150,-209 150,99, height 639
PLD10-254PX1278X254X854N [mil]
  rrect5% 63x63 hole 43.31 mask+2.76: 1(200,50)
  round 63 hole 43.31 mask+2.76: 2(200,-50) 3(100,50) 4(100,-50) 5(0,50) 6(0,-50) 7(-100,50) 8(-100,-50) 9(-200,50) 10(-200,-50)
  silkscreen extent -252,-100 283,100, body extent -250,-101 250,205, height 639
PLD20-254PX2548X254X854N [mil]
  rrect5% 63x63 hole 43.31 mask+2.76: 1(450,50)
  round 63 hole 43.31 mask+2.76: 2(450,-50) 3(350,50) 4(350,-50) 5(250,50) 6(250,-50) 7(150,50) 8(150,-50) 9(50,50) 10(50,-50) 11(-50,50) 12(-50,-50) 13(-150,50) 14(-150,-50) 15(-250,50) 16(-250,-50) 17(-350,50) 18(-350,-50) 19(-450,50) 20(-450,-50)
  silkscreen extent -502,-100 533,100, body extent -500,-100 500,100, height 330
PLD38-254PX4834X254X854N [mil]
  rrect5% 63x63 hole 43.31 mask+2.76: 1(900,50)
  round 63 hole 43.31 mask+2.76: 2(900,-50) 3(800,50) 4(800,-50) 5(700,50) 6(700,-50) 7(600,50) 8(600,-50) 9(500,50) 10(500,-50) 11(400,50) 12(400,-50) 13(300,50) 14(300,-50) 15(200,50) 16(200,-50) 17(100,50) 18(100,-50) 19(0,50) 20(0,-50) 21(-100,50) 22(-100,-50) 23(-200,50) 24(-200,-50) 25(-300,50) 26(-300,-50) 27(-400,50) 28(-400,-50) 29(-500,50) 30(-500,-50) 31(-600,50) 32(-600,-50) 33(-700,50) 34(-700,-50) 35(-800,50) 36(-800,-50) 37(-900,50) 38(-900,-50)
  silkscreen extent -952,-100 983,100, body extent -950,-100 950,100, height 330
PLS2-254PX50X25X854N [mil]
  rrect5% 63x63 hole 43.31 mask+2.76: 1(-50,0)
  round 63 hole 43.31 mask+2.76: 2(50,0)
  silkscreen extent -130,-50 100,50, body extent -100,-50 100,50, height 337
PLS3-254PX76X25X854N [mil]
  rrect5% 63x63 hole 43.31 mask+2.76: 1(-100,0)
  round 63 hole 43.31 mask+2.76: 2(0,0) 3(100,0)
  silkscreen extent -180,-50 150,50, body extent -150,-50 150,50, height 337
PW0014A_L [mm] "SOP, 14-Leads, Body 5.1x4.5mm, Pitch 0.65mm, IPC High Density"
  rrect25% 1.2x0.4 smd: 1(-2.85,1.95) 2(-2.85,1.3) 3(-2.85,0.65) 4(-2.85,0) 5(-2.85,-0.65) 6(-2.85,-1.3) 7(-2.85,-1.95) 8(2.85,-1.95) 9(2.85,-1.3) 10(2.85,-0.65) 11(2.85,0) 12(2.85,0.65) 13(2.85,1.3) 14(2.85,1.95)
  silkscreen extent -2.97,-2.55 1.85,2.82, body extent -3.21,-2.5 3.21,2.5, height 1
QFNWB10X10-88L-AL [mm]
  rrect25% 0.92x0.24 smd: 1(-4.905,4.2) 2(-4.905,3.8) 3(-4.905,3.4) 4(-4.905,3) 5(-4.905,2.6) 6(-4.905,2.2) 7(-4.905,1.8) 8(-4.905,1.4) 9(-4.905,1) 10(-4.905,0.6) 11(-4.905,0.2) 12(-4.905,-0.2) 13(-4.905,-0.6) 14(-4.905,-1) 15(-4.905,-1.4) 16(-4.905,-1.8) 17(-4.905,-2.2) 18(-4.905,-2.6) 19(-4.905,-3) 20(-4.905,-3.4) 21(-4.905,-3.8) 22(-4.905,-4.2) 45(4.905,-4.2) 46(4.905,-3.8) 47(4.905,-3.4) 48(4.905,-3) 49(4.905,-2.6) 50(4.905,-2.2) 51(4.905,-1.8) 52(4.905,-1.4) 53(4.905,-1) 54(4.905,-0.6) 55(4.905,-0.2) 56(4.905,0.2) 57(4.905,0.6) 58(4.905,1) 59(4.905,1.4) 60(4.905,1.8) 61(4.905,2.2) 62(4.905,2.6) 63(4.905,3) 64(4.905,3.4) 65(4.905,3.8) 66(4.905,4.2)
  rrect25% 0.24x0.92 smd: 23(-4.2,-4.905) 24(-3.8,-4.905) 25(-3.4,-4.905) 26(-3,-4.905) 27(-2.6,-4.905) 28(-2.2,-4.905) 29(-1.8,-4.905) 30(-1.4,-4.905) 31(-1,-4.905) 32(-0.6,-4.905) 33(-0.2,-4.905) 34(0.2,-4.905) 35(0.6,-4.905) 36(1,-4.905) 37(1.4,-4.905) 38(1.8,-4.905) 39(2.2,-4.905) 40(2.6,-4.905) 41(3,-4.905) 42(3.4,-4.905) 43(3.8,-4.905) 44(4.2,-4.905) 67(4.2,4.905) 68(3.8,4.905) 69(3.4,4.905) 70(3,4.905) 71(2.6,4.905) 72(2.2,4.905) 73(1.8,4.905) 74(1.4,4.905) 75(1,4.905) 76(0.6,4.905) 77(0.2,4.905) 78(-0.2,4.905) 79(-0.6,4.905) 80(-1,4.905) 81(-1.4,4.905) 82(-1.8,4.905) 83(-2.2,4.905) 84(-2.6,4.905) 85(-3,4.905) 86(-3.4,4.905) 87(-3.8,4.905) 88(-4.2,4.905)
  rect 7.112x7.112 smd paste-3: 89(0,0)
  silkscreen extent -6.12,-5.05 5.05,5.05, body extent -5,-5 5,5, height 0.85
QFP50P1200X1200X160-64N [mm]
  rect 1.475x0.3 smd: 1(-5.738,3.75) 2(-5.738,3.25) 3(-5.738,2.75) 4(-5.738,2.25) 5(-5.738,1.75) 6(-5.738,1.25) 7(-5.738,0.75) 8(-5.738,0.25) 9(-5.738,-0.25) 10(-5.738,-0.75) 11(-5.738,-1.25) 12(-5.738,-1.75) 13(-5.738,-2.25) 14(-5.738,-2.75) 15(-5.738,-3.25) 16(-5.738,-3.75) 33(5.738,-3.75) 34(5.738,-3.25) 35(5.738,-2.75) 36(5.738,-2.25) 37(5.738,-1.75) 38(5.738,-1.25) 39(5.738,-0.75) 40(5.738,-0.25) 41(5.738,0.25) 42(5.738,0.75) 43(5.738,1.25) 44(5.738,1.75) 45(5.738,2.25) 46(5.738,2.75) 47(5.738,3.25) 48(5.738,3.75)
  rect 0.3x1.475 smd: 17(-3.75,-5.738) 18(-3.25,-5.738) 19(-2.75,-5.738) 20(-2.25,-5.738) 21(-1.75,-5.738) 22(-1.25,-5.738) 23(-0.75,-5.738) 24(-0.25,-5.738) 25(0.25,-5.738) 26(0.75,-5.738) 27(1.25,-5.738) 28(1.75,-5.738) 29(2.25,-5.738) 30(2.75,-5.738) 31(3.25,-5.738) 32(3.75,-5.738) 49(3.75,5.738) 50(3.25,5.738) 51(2.75,5.738) 52(2.25,5.738) 53(1.75,5.738) 54(1.25,5.738) 55(0.75,5.738) 56(0.25,5.738) 57(-0.25,5.738) 58(-0.75,5.738) 59(-1.25,5.738) 60(-1.75,5.738) 61(-2.25,5.738) 62(-2.75,5.738) 63(-3.25,5.738) 64(-3.75,5.738)
  silkscreen extent -6.35,-4.65 4.65,4.65, body extent -6,-6 6,6, height 1.6
RESC1608X45N [mm]
  rrect5% 0.9x0.95 smd mask+0.07: 1(-0.8,0) 2(0.8,0)
  silkscreen extent -1.4,-0.63 1.4,0.63, body extent -0.85,-0.45 0.85,0.45, height 0.55
SMBJ12A [mm]
  rect 2.2x2.15 smd: 1(-2.2,0) 2(2.2,0)
  silkscreen extent -2.68,-1.81 2.68,1.81, body extent -2.68,-1.86 2.68,1.86, height 2.33
SOD2512X80N [mm]
  rect 1.1x0.5 smd: 1(-1.15,0) 2(1.15,0)
  silkscreen extent -1.7,-0.63 0.85,0.63, body extent -1.25,-0.63 1.25,0.63, height 0.8
SOIC127P790X216-8N [mm]
  rect 1.65x0.65 smd: 1(-3.6,1.905) 2(-3.6,0.635) 3(-3.6,-0.635) 4(-3.6,-1.905) 5(3.6,-1.905) 6(3.6,-0.635) 7(3.6,0.635) 8(3.6,1.905)
  silkscreen extent -4.43,-2.64 2.42,2.64, body extent -3.95,-2.64 3.95,2.64, height 2.16
SOP50P490X110-11N [mm]
  rect 1.4x0.3 smd: 1(-2.2,1) 2(-2.2,0.5) 3(-2.2,0) 4(-2.2,-0.5) 5(-2.2,-1) 6(2.2,-1) 7(2.2,-0.5) 8(2.2,0) 9(2.2,0.5) 10(2.2,1)
  rect 1.57x1.88 smd: 11(0,0)
  silkscreen extent -2.9,1.5 -1.5,1.5, body extent -2.46,-1.5 2.46,1.5, height 0.96
SOT65P210X110-5N [mm]
  rect 1x0.4 smd: 1(-1,0.65) 2(-1,0) 3(-1,-0.65) 4(1,-0.65) 5(1,0.65)
  silkscreen extent -1.5,-1 0.15,1.1, body extent -1.05,-1 1.05,1, height 1.1
SOT95P230X110-3N [mm] "SOT95P230X110-3N"
  rrect5% 1x0.6 smd mask+0.05: 1(-1.15,0.95) 2(-1.15,-0.95) 3(1.15,0)
  silkscreen extent -1.52,-1.45 0.33,1.87, body extent -1.35,-1.55 1.35,1.55, height 1.1
SOT95P280X145-5N [mm]
  rect 1.2x0.6 smd: 1(-1.25,0.95) 2(-1.25,0) 3(-1.25,-0.95) 4(1.25,-0.95) 5(1.25,0.95)
  silkscreen extent -1.85,-1.45 0.3,1.5, body extent -1.4,-1.45 1.4,1.45, height 1.2
SOT95P280X145-6N [mm]
  rrect5% 1.12x0.61 smd mask+0.05: 1(-1.2,0.95) 2(-1.2,0) 3(-1.2,-0.95) 4(1.2,-0.95) 5(1.2,0) 6(1.2,0.95)
  silkscreen extent -1.6,-1.7 0.9,1.95, body extent -1.42,-1.55 1.42,1.55, height 1.46
SOT95P285X140-5N [mm]
  rect 1.15x0.6 smd: 1(-1.3,0.95) 2(-1.3,0) 3(-1.3,-0.95) 4(1.3,-0.95) 5(1.3,0.95)
  silkscreen extent -1.88,-1.5 0.38,1.5, body extent -1.43,-1.5 1.43,1.5, height 1.4
TUSB320RWBR [mm]
  rect 0.7x0.2 smd: 1(-0.65,0.2) 2(-0.65,-0.2) 7(0.65,-0.2) 8(0.65,0.2)
  rect 0.2x0.5 smd: 3(-0.6,-0.75) 4(-0.2,-0.75) 5(0.2,-0.75) 6(0.6,-0.75) 9(0.6,0.75) 10(0.2,0.75) 11(-0.2,0.75) 12(-0.6,0.75)
  silkscreen extent -1.58,-0.8 0.8,0.8, body extent -0.8,-0.8 0.8,0.8, height 0.5
TYPE-C-31-M-12 [mm] "USB TYPE-C 5A 16P Female SMD USB Connectors"
  rrect15% 0.6x1.3 smd mask+0.05: A1_B12(0,0.1) A4_B9(0.8,0.1) B1_A12(6.4,0.1) B4_A9(5.6,0.1)
  rrect15% 0.3x1.3 smd mask+0.05: A5(1.95,0.1) A6(2.95,0.1) A7(3.45,0.1) A8(4.45,0.1) B5(4.95,0.1) B6(3.95,0.1) B7(2.45,0.1) B8(1.45,0.1)
  oval 0.9x2 hole 0.6 slot 1.7 at 90 deg mask+0.05: S1(-1.125,-0.57) S3(7.525,-0.57)
  oval 0.9x1.7 hole 0.6 slot 1.4 at 90 deg mask+0.05: S2(-1.125,-4.75) S4(7.525,-4.75)
  round 0 hole 0.7 unplated: ""(0.31,-1.07) ""(6.09,-1.07)
  Top Layer keep-out region: -0.25,-7.275 6.75,-7.275 6.75,-1.625 -0.25,-1.625
  silkscreen extent -1.3,-7.53 7.7,-1.78, body extent -1.27,-7.35 7.68,0.55, height 3.16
